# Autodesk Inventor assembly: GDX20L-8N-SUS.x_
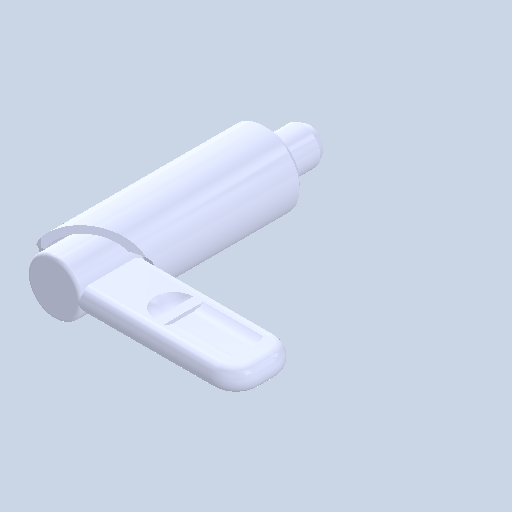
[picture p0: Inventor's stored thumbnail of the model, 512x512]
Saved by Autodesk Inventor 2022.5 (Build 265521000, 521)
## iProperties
Created: 2024-06
Part Number: GDX20L-8N-SUS.x_
Document SubType Name: Assembly
Designer: ImaoCorp
Author: ImaoCorp
Sending System: SOLIDWORKS 2022-2022290
MC: AMD64
MC_MODEL: Intel64 Family 6 Model 60 Stepping 3, GenuineIntel
OS: Windows_NT
FRU: Parasolid Version 33.1, build 260,  4-25-2022
FORMAT: text
GUISE: transmit
KEY: FILEGDX20L-8N-SUS.x_t
DATE: Wed Jun 12 09:32:56 2024
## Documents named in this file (3)
- Y:\5.更新分\2024年対応\xxxx_GDX\データ_imao品番\gdx20l-8n-sus\GDX20L-8N-SUS.x_.iam
- Y:\5.更新分\2024年対応\xxxx_GDX\データ_imao品番\gdx20l-8n-sus\GDX20L-8N-SUS_01.ipt
- Y:\5.更新分\2024年対応\xxxx_GDX\データ_imao品番\gdx20l-8n-sus\GDX20L-8N-SUS_02.ipt
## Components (2 placed, 2 different names)
1. GDX20L-8N-SUS_01
2. GDX20L-8N-SUS_02
